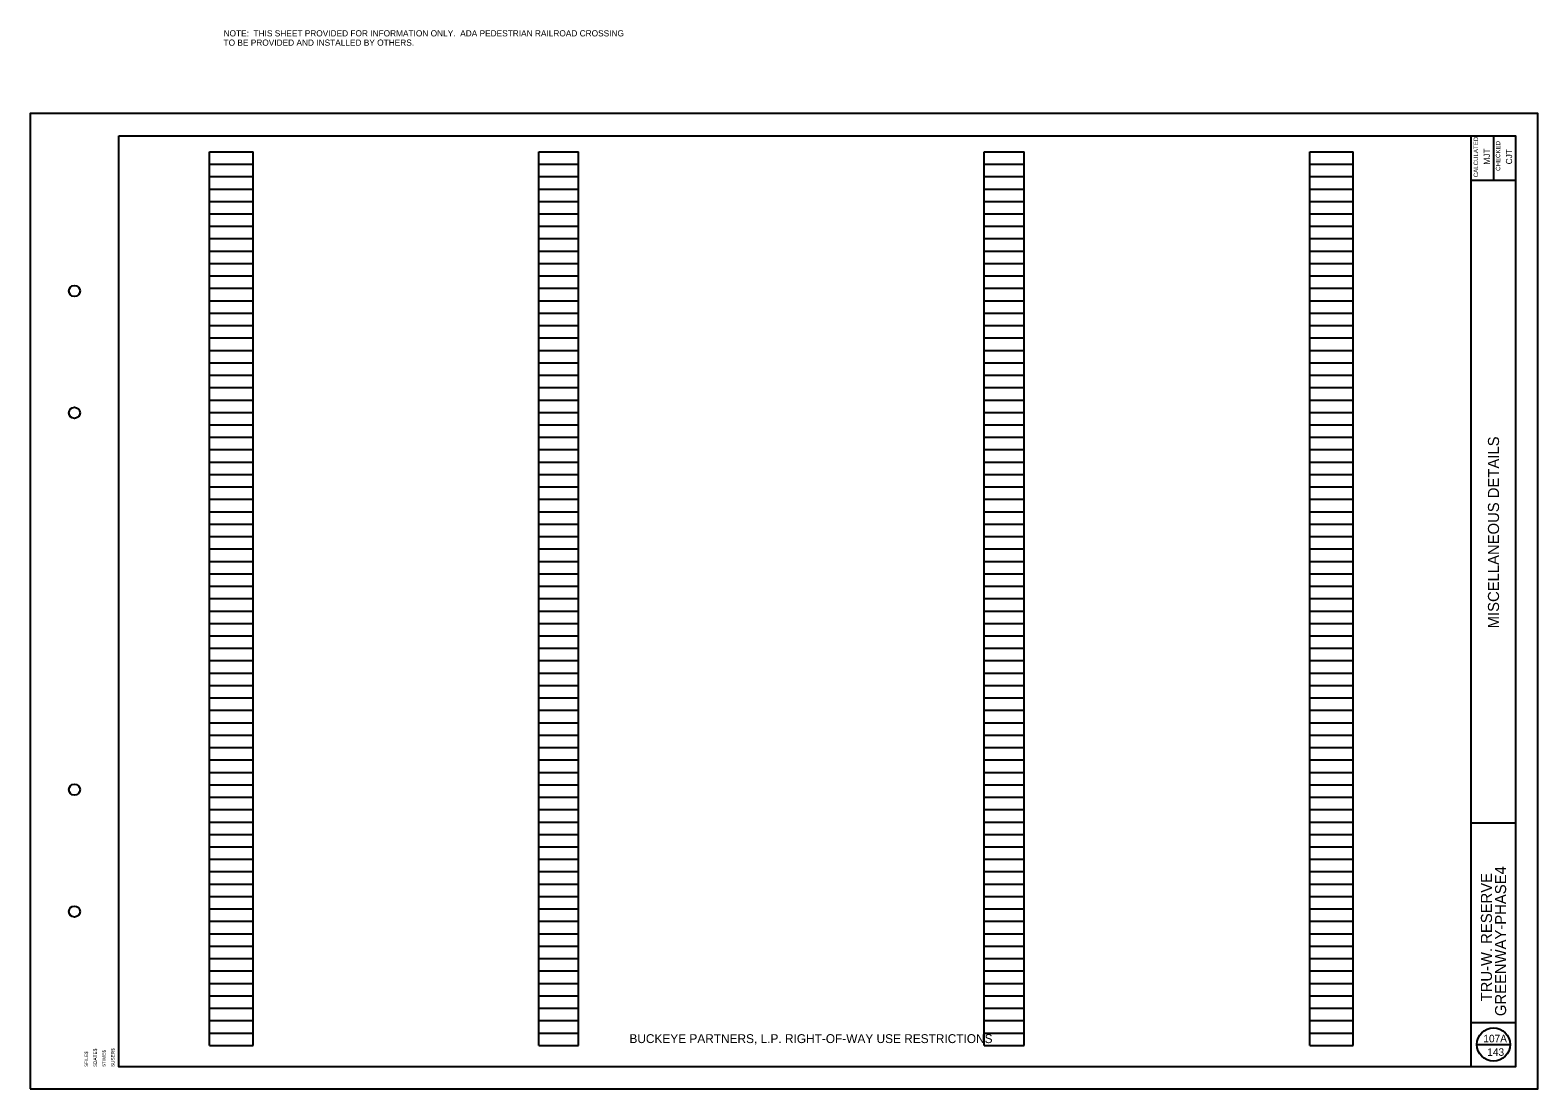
# Model space of a CAD drawing. Extents: x 30 to 362, y -13 to 11.
# Drawn here: x 49.77 to 83.77, y -12.91 to 10.98 of the extents above; entities that cross this region are included whole.
import ezdxf

# ---------------------------------------------------------------- set-up
doc = ezdxf.new("R2010")
doc.units = 0
for name, color, linetype in [('SH_Border', 7, 'Continuous'), ('SH_Cut_Line', 7, 'Continuous'), ('SH_Data', 7, 'Continuous'), ('TX_P_1', 7, 'Continuous'), ('TX_P_Misc', 7, 'Continuous')]:
    doc.layers.add(name, color=color, linetype=linetype)

msp = doc.modelspace()

# ---------------------------------------------------------------- linework, layer by layer
at = {"layer": 'SH_Border'}
for p, q in [((82.274, -12.407), (82.274, 8.593)), ((82.774, 8.593), (82.774, 7.593)), ((82.274, 7.593), (83.274, 7.593)), ((82.274, -6.907), (83.274, -6.907)), ((82.274, -11.407), (83.274, -11.407))]:
    msp.add_line(p, q, dxfattribs=at)
msp.add_lwpolyline([(51.774, 8.593), (83.274, 8.593), (83.274, -12.407), (51.774, -12.407)], close=True, dxfattribs=at)
for centre in [(50.774, 5.093), (50.774, 2.343), (50.774, -6.157), (50.774, -8.907)]:
    msp.add_circle(centre, 0.125, dxfattribs=at)
at = {"layer": 'SH_Cut_Line'}
msp.add_lwpolyline([(49.774, -12.907), (83.774, -12.907), (83.774, 9.093), (49.774, 9.093)], close=True, dxfattribs=at)
at = {"layer": 'SH_Data'}
for p, q in [((53.822, -11.927), (53.822, 8.233)), ((53.822, 8.233), (54.802, 8.233)), ((54.802, -11.927), (54.802, 8.233)), ((61.242, -11.927), (61.242, 8.233)), ((61.242, 8.233), (62.142, 8.233)), ((62.142, -11.927), (62.142, 8.233)), ((71.29, -11.927), (71.29, 8.233)), ((71.29, 8.233), (72.19, 8.233)), ((72.19, -11.927), (72.19, 8.233)), ((78.63, -11.927), (78.63, 8.233)), ((78.63, 8.233), (79.61, 8.233)), ((79.61, -11.927), (79.61, 8.233)), ((53.822, 7.953), (54.802, 7.953)), ((61.242, 7.953), (62.142, 7.953)), ((71.29, 7.953), (72.19, 7.953)), ((78.63, 7.953), (79.61, 7.953)), ((53.822, 7.673), (54.802, 7.673)), ((61.242, 7.673), (62.142, 7.673)), ((71.29, 7.673), (72.19, 7.673)), ((78.63, 7.673), (79.61, 7.673)), ((53.822, 7.393), (54.802, 7.393)), ((61.242, 7.393), (62.142, 7.393)), ((71.29, 7.393), (72.19, 7.393)), ((78.63, 7.393), (79.61, 7.393)), ((53.822, 7.113), (54.802, 7.113)), ((53.822, 6.833), (54.802, 6.833)), ((61.242, 7.113), (62.142, 7.113)), ((61.242, 6.833), (62.142, 6.833)), ((71.29, 7.113), (72.19, 7.113)), ((71.29, 6.833), (72.19, 6.833)), ((78.63, 7.113), (79.61, 7.113)), ((78.63, 6.833), (79.61, 6.833)), ((53.822, 6.553), (54.802, 6.553)), ((61.242, 6.553), (62.142, 6.553)), ((71.29, 6.553), (72.19, 6.553)), ((78.63, 6.553), (79.61, 6.553)), ((53.822, 6.273), (54.802, 6.273)), ((61.242, 6.273), (62.142, 6.273)), ((71.29, 6.273), (72.19, 6.273)), ((78.63, 6.273), (79.61, 6.273)), ((53.822, 5.993), (54.802, 5.993)), ((61.242, 5.993), (62.142, 5.993)), ((71.29, 5.993), (72.19, 5.993)), ((78.63, 5.993), (79.61, 5.993)), ((53.822, 5.713), (54.802, 5.713)), ((61.242, 5.713), (62.142, 5.713)), ((71.29, 5.713), (72.19, 5.713)), ((78.63, 5.713), (79.61, 5.713)), ((53.822, 5.433), (54.802, 5.433)), ((53.822, 5.153), (54.802, 5.153)), ((61.242, 5.433), (62.142, 5.433)), ((61.242, 5.153), (62.142, 5.153)), ((71.29, 5.433), (72.19, 5.433)), ((71.29, 5.153), (72.19, 5.153)), ((78.63, 5.433), (79.61, 5.433)), ((78.63, 5.153), (79.61, 5.153)), ((53.822, 4.873), (54.802, 4.873)), ((61.242, 4.873), (62.142, 4.873)), ((71.29, 4.873), (72.19, 4.873)), ((78.63, 4.873), (79.61, 4.873)), ((53.822, 4.593), (54.802, 4.593)), ((61.242, 4.593), (62.142, 4.593)), ((71.29, 4.593), (72.19, 4.593)), ((78.63, 4.593), (79.61, 4.593)), ((53.822, 4.313), (54.802, 4.313)), ((61.242, 4.313), (62.142, 4.313)), ((71.29, 4.313), (72.19, 4.313)), ((78.63, 4.313), (79.61, 4.313)), ((53.822, 4.033), (54.802, 4.033)), ((53.822, 3.753), (54.802, 3.753)), ((61.242, 4.033), (62.142, 4.033)), ((61.242, 3.753), (62.142, 3.753)), ((71.29, 4.033), (72.19, 4.033)), ((71.29, 3.753), (72.19, 3.753)), ((78.63, 4.033), (79.61, 4.033)), ((78.63, 3.753), (79.61, 3.753)), ((53.822, 3.473), (54.802, 3.473)), ((61.242, 3.473), (62.142, 3.473)), ((71.29, 3.473), (72.19, 3.473)), ((78.63, 3.473), (79.61, 3.473)), ((53.822, 3.193), (54.802, 3.193)), ((61.242, 3.193), (62.142, 3.193)), ((71.29, 3.193), (72.19, 3.193)), ((78.63, 3.193), (79.61, 3.193)), ((53.822, 2.913), (54.802, 2.913)), ((61.242, 2.913), (62.142, 2.913)), ((71.29, 2.913), (72.19, 2.913)), ((78.63, 2.913), (79.61, 2.913)), ((53.822, 2.633), (54.802, 2.633)), ((61.242, 2.633), (62.142, 2.633)), ((71.29, 2.633), (72.19, 2.633)), ((78.63, 2.633), (79.61, 2.633)), ((53.822, 2.353), (54.802, 2.353)), ((53.822, 2.073), (54.802, 2.073)), ((61.242, 2.353), (62.142, 2.353)), ((61.242, 2.073), (62.142, 2.073)), ((71.29, 2.353), (72.19, 2.353)), ((71.29, 2.073), (72.19, 2.073)), ((78.63, 2.353), (79.61, 2.353)), ((78.63, 2.073), (79.61, 2.073)), ((53.822, 1.793), (54.802, 1.793)), ((61.242, 1.793), (62.142, 1.793)), ((71.29, 1.793), (72.19, 1.793)), ((78.63, 1.793), (79.61, 1.793)), ((53.822, 1.513), (54.802, 1.513)), ((61.242, 1.513), (62.142, 1.513)), ((71.29, 1.513), (72.19, 1.513)), ((78.63, 1.513), (79.61, 1.513)), ((53.822, 1.233), (54.802, 1.233)), ((61.242, 1.233), (62.142, 1.233)), ((71.29, 1.233), (72.19, 1.233)), ((78.63, 1.233), (79.61, 1.233)), ((53.822, 0.953), (54.802, 0.953)), ((61.242, 0.953), (62.142, 0.953)), ((71.29, 0.953), (72.19, 0.953)), ((78.63, 0.953), (79.61, 0.953)), ((53.822, 0.673), (54.802, 0.673)), ((53.822, 0.393), (54.802, 0.393)), ((61.242, 0.673), (62.142, 0.673)), ((61.242, 0.393), (62.142, 0.393)), ((71.29, 0.673), (72.19, 0.673)), ((71.29, 0.393), (72.19, 0.393)), ((78.63, 0.673), (79.61, 0.673)), ((78.63, 0.393), (79.61, 0.393)), ((53.822, 0.113), (54.802, 0.113)), ((61.242, 0.113), (62.142, 0.113)), ((71.29, 0.113), (72.19, 0.113)), ((78.63, 0.113), (79.61, 0.113)), ((53.822, -0.167), (54.802, -0.167)), ((61.242, -0.167), (62.142, -0.167)), ((71.29, -0.167), (72.19, -0.167)), ((78.63, -0.167), (79.61, -0.167)), ((53.822, -0.447), (54.802, -0.447)), ((61.242, -0.447), (62.142, -0.447)), ((71.29, -0.447), (72.19, -0.447)), ((78.63, -0.447), (79.61, -0.447)), ((53.822, -0.727), (54.802, -0.727)), ((53.822, -1.007), (54.802, -1.007)), ((61.242, -0.727), (62.142, -0.727)), ((61.242, -1.007), (62.142, -1.007)), ((71.29, -0.727), (72.19, -0.727)), ((71.29, -1.007), (72.19, -1.007)), ((78.63, -0.727), (79.61, -0.727)), ((78.63, -1.007), (79.61, -1.007)), ((53.822, -1.287), (54.802, -1.287)), ((61.242, -1.287), (62.142, -1.287)), ((71.29, -1.287), (72.19, -1.287)), ((78.63, -1.287), (79.61, -1.287)), ((53.822, -1.567), (54.802, -1.567)), ((61.242, -1.567), (62.142, -1.567)), ((71.29, -1.567), (72.19, -1.567)), ((78.63, -1.567), (79.61, -1.567)), ((53.822, -1.847), (54.802, -1.847)), ((61.242, -1.847), (62.142, -1.847)), ((71.29, -1.847), (72.19, -1.847)), ((78.63, -1.847), (79.61, -1.847)), ((53.822, -2.127), (54.802, -2.127)), ((61.242, -2.127), (62.142, -2.127)), ((71.29, -2.127), (72.19, -2.127)), ((78.63, -2.127), (79.61, -2.127)), ((53.822, -2.407), (54.802, -2.407)), ((53.822, -2.687), (54.802, -2.687)), ((61.242, -2.407), (62.142, -2.407)), ((61.242, -2.687), (62.142, -2.687)), ((71.29, -2.407), (72.19, -2.407)), ((71.29, -2.687), (72.19, -2.687)), ((78.63, -2.407), (79.61, -2.407)), ((78.63, -2.687), (79.61, -2.687)), ((53.822, -2.967), (54.802, -2.967)), ((61.242, -2.967), (62.142, -2.967)), ((71.29, -2.967), (72.19, -2.967)), ((78.63, -2.967), (79.61, -2.967)), ((53.822, -3.247), (54.802, -3.247)), ((61.242, -3.247), (62.142, -3.247)), ((71.29, -3.247), (72.19, -3.247)), ((78.63, -3.247), (79.61, -3.247)), ((53.822, -3.527), (54.802, -3.527)), ((61.242, -3.527), (62.142, -3.527)), ((71.29, -3.527), (72.19, -3.527)), ((78.63, -3.527), (79.61, -3.527)), ((53.822, -3.807), (54.802, -3.807)), ((61.242, -3.807), (62.142, -3.807)), ((71.29, -3.807), (72.19, -3.807)), ((78.63, -3.807), (79.61, -3.807)), ((53.822, -4.087), (54.802, -4.087)), ((53.822, -4.367), (54.802, -4.367)), ((61.242, -4.087), (62.142, -4.087)), ((61.242, -4.367), (62.142, -4.367)), ((71.29, -4.087), (72.19, -4.087)), ((71.29, -4.367), (72.19, -4.367)), ((78.63, -4.087), (79.61, -4.087)), ((78.63, -4.367), (79.61, -4.367)), ((53.822, -4.647), (54.802, -4.647)), ((61.242, -4.647), (62.142, -4.647)), ((71.29, -4.647), (72.19, -4.647)), ((78.63, -4.647), (79.61, -4.647)), ((53.822, -4.927), (54.802, -4.927)), ((61.242, -4.927), (62.142, -4.927)), ((71.29, -4.927), (72.19, -4.927)), ((78.63, -4.927), (79.61, -4.927)), ((53.822, -5.207), (54.802, -5.207)), ((61.242, -5.207), (62.142, -5.207)), ((71.29, -5.207), (72.19, -5.207)), ((78.63, -5.207), (79.61, -5.207)), ((53.822, -5.487), (54.802, -5.487)), ((53.822, -5.767), (54.802, -5.767)), ((61.242, -5.487), (62.142, -5.487)), ((61.242, -5.767), (62.142, -5.767)), ((71.29, -5.487), (72.19, -5.487)), ((71.29, -5.767), (72.19, -5.767)), ((78.63, -5.487), (79.61, -5.487)), ((78.63, -5.767), (79.61, -5.767)), ((53.822, -6.047), (54.802, -6.047)), ((61.242, -6.047), (62.142, -6.047)), ((71.29, -6.047), (72.19, -6.047)), ((78.63, -6.047), (79.61, -6.047)), ((53.822, -6.327), (54.802, -6.327)), ((61.242, -6.327), (62.142, -6.327)), ((71.29, -6.327), (72.19, -6.327)), ((78.63, -6.327), (79.61, -6.327)), ((53.822, -6.607), (54.802, -6.607)), ((61.242, -6.607), (62.142, -6.607)), ((71.29, -6.607), (72.19, -6.607)), ((78.63, -6.607), (79.61, -6.607)), ((53.822, -6.887), (54.802, -6.887)), ((61.242, -6.887), (62.142, -6.887)), ((71.29, -6.887), (72.19, -6.887)), ((78.63, -6.887), (79.61, -6.887)), ((53.822, -7.167), (54.802, -7.167)), ((53.822, -7.447), (54.802, -7.447)), ((61.242, -7.167), (62.142, -7.167)), ((61.242, -7.447), (62.142, -7.447)), ((71.29, -7.167), (72.19, -7.167)), ((71.29, -7.447), (72.19, -7.447)), ((78.63, -7.167), (79.61, -7.167)), ((78.63, -7.447), (79.61, -7.447)), ((53.822, -7.727), (54.802, -7.727)), ((61.242, -7.727), (62.142, -7.727)), ((71.29, -7.727), (72.19, -7.727)), ((78.63, -7.727), (79.61, -7.727)), ((53.822, -8.007), (54.802, -8.007)), ((61.242, -8.007), (62.142, -8.007)), ((71.29, -8.007), (72.19, -8.007)), ((78.63, -8.007), (79.61, -8.007)), ((53.822, -8.287), (54.802, -8.287)), ((61.242, -8.287), (62.142, -8.287)), ((71.29, -8.287), (72.19, -8.287)), ((78.63, -8.287), (79.61, -8.287)), ((53.822, -8.567), (54.802, -8.567)), ((61.242, -8.567), (62.142, -8.567)), ((71.29, -8.567), (72.19, -8.567)), ((78.63, -8.567), (79.61, -8.567)), ((53.822, -8.847), (54.802, -8.847)), ((53.822, -9.127), (54.802, -9.127)), ((61.242, -8.847), (62.142, -8.847)), ((61.242, -9.127), (62.142, -9.127)), ((71.29, -8.847), (72.19, -8.847)), ((71.29, -9.127), (72.19, -9.127)), ((78.63, -8.847), (79.61, -8.847)), ((78.63, -9.127), (79.61, -9.127)), ((53.822, -9.407), (54.802, -9.407)), ((61.242, -9.407), (62.142, -9.407)), ((71.29, -9.407), (72.19, -9.407)), ((78.63, -9.407), (79.61, -9.407)), ((53.822, -9.687), (54.802, -9.687)), ((61.242, -9.687), (62.142, -9.687)), ((71.29, -9.687), (72.19, -9.687)), ((78.63, -9.687), (79.61, -9.687)), ((53.822, -9.967), (54.802, -9.967)), ((61.242, -9.967), (62.142, -9.967)), ((71.29, -9.967), (72.19, -9.967)), ((78.63, -9.967), (79.61, -9.967)), ((53.822, -10.247), (54.802, -10.247)), ((53.822, -10.527), (54.802, -10.527)), ((61.242, -10.247), (62.142, -10.247)), ((61.242, -10.527), (62.142, -10.527)), ((71.29, -10.247), (72.19, -10.247)), ((71.29, -10.527), (72.19, -10.527)), ((78.63, -10.247), (79.61, -10.247)), ((78.63, -10.527), (79.61, -10.527)), ((53.822, -10.807), (54.802, -10.807)), ((61.242, -10.807), (62.142, -10.807)), ((71.29, -10.807), (72.19, -10.807)), ((78.63, -10.807), (79.61, -10.807)), ((53.822, -11.087), (54.802, -11.087)), ((61.242, -11.087), (62.142, -11.087)), ((71.29, -11.087), (72.19, -11.087)), ((78.63, -11.087), (79.61, -11.087)), ((53.822, -11.367), (54.802, -11.367)), ((61.242, -11.367), (62.142, -11.367)), ((71.29, -11.367), (72.19, -11.367)), ((78.63, -11.367), (79.61, -11.367)), ((53.822, -11.647), (54.802, -11.647)), ((61.242, -11.647), (62.142, -11.647)), ((71.29, -11.647), (72.19, -11.647)), ((78.63, -11.647), (79.61, -11.647)), ((53.822, -11.927), (54.802, -11.927)), ((61.242, -11.927), (62.142, -11.927)), ((71.29, -11.927), (72.19, -11.927)), ((78.63, -11.927), (79.61, -11.927)), ((82.399, -11.907), (83.149, -11.907)), ((69.29, -12.907), (69.29, -12.907))]:
    msp.add_line(p, q, dxfattribs=at)
msp.add_circle((82.774, -11.907), 0.375, dxfattribs=at)

# ---------------------------------------------------------------- texts
for s, height, p in [('CALCULATED', 0.1, (82.427, 7.658)), ('MJT', 0.14, (82.694, 7.942)), ('CHECKED', 0.1, (82.927, 7.801)), ('CJT', 0.14, (83.194, 7.949)), ('MISCELLANEOUS DETAILS', 0.25, (82.899, -2.518)), ('TRU-W. RESERVE', 0.25, (82.74, -10.934)), ('GREENWAY-PHASE4', 0.25, (83.059, -11.266))]:
    msp.add_text(s, height=height, rotation=90, dxfattribs=at).set_placement(p)
for s, p in [('107A', (82.546, -11.857)), ('143', (82.634, -12.162))]:
    msp.add_text(s, height=0.17, dxfattribs=at).set_placement(p)
at = {"layer": 'TX_P_1'}
for s, height, p in [('NOTE:  THIS SHEET PROVIDED FOR INFORMATION ONLY.  ADA PEDESTRIAN RAILROAD CROSSING', 0.14, (54.136, 10.835)), ('TO BE PROVIDED AND INSTALLED BY OTHERS.', 0.14, (54.136, 10.625)), ('BUCKEYE PARTNERS, L.P. RIGHT-OF-WAY USE RESTRICTIONS', 0.2, (63.289, -11.874))]:
    msp.add_text(s, height=height, dxfattribs=at).set_placement(p)
at = {"layer": 'TX_P_Misc'}
for s, p in [('$FILE$', (51.079, -12.407)), ('$DATE$', (51.279, -12.407)), ('$TIME$', (51.479, -12.407)), ('$USER$', (51.679, -12.407))]:
    msp.add_text(s, height=0.078, rotation=90, dxfattribs=at).set_placement(p)

doc.saveas('drawing.dxf')
